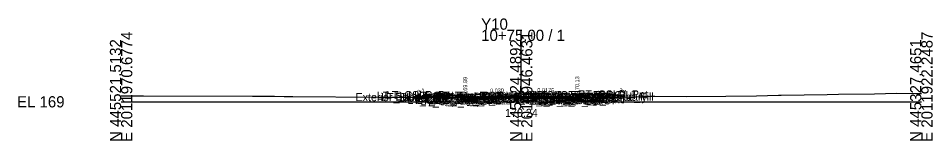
# Model space of a CAD drawing. Extents: x -26 to 203, y -10 to 3517.
# Drawn here: x -25.7 to 202.8, y 1490.3 to 1520.8 of the extents above; entities that cross this region are included whole.
import ezdxf

# ---------------------------------------------------------------- set-up
doc = ezdxf.new("R2010")
doc.units = 0
for name, color, linetype in [('Default', 7, 'Continuous'), ('Exist CMT Pavement', 7, 'Continuous'), ('Exist Cross Section Cell', 7, 'Continuous'), ('Exist XS Center Line Elevation Label', 7, 'Continuous'), ('Exist XS Ground Line', 7, 'Continuous'), ('Prop CMT Conc Surface', 7, 'Continuous'), ('Prop CMT Concrete Structures', 7, 'Continuous'), ('Prop CMT Pvmt Course 1', 7, 'Continuous'), ('Prop CMT Pvmt Course 1 CG', 7, 'Continuous'), ('Prop CMT Pvmt Course 1 Wedge', 7, 'Continuous'), ('Prop CMT Pvmt Course 2', 7, 'Continuous'), ('Prop CMT Pvmt Course 2 Wedge', 7, 'Continuous'), ('Prop CMT Pvmt Course 3', 7, 'Continuous'), ('Prop CMT Pvmt Surface', 7, 'Continuous'), ('Prop CMT Pvmt Wedge Surface 1', 7, 'Continuous'), ('Prop CMT Pvmt Wedge Surface 2', 7, 'Continuous'), ('Prop CMT Pvmt Wedge Surface 3', 7, 'Continuous'), ('Prop CMT Slope Grass', 7, 'Continuous'), ('Prop CMT Subgrade Earthwork', 7, 'Continuous'), ('Prop XS Earthwork Shape', 7, 'Continuous'), ('Prop XS Hydro Elevations', 7, 'Continuous'), ('Prop XS SE Text', 7, 'Continuous'), ('Prop XS Side Slope Text', 7, 'Continuous'), ('Prop XS Wedging', 7, 'Continuous'), ('Scratch_Level_0', 7, 'Continuous')]:
    doc.layers.add(name, color=color, linetype=linetype)

msp = doc.modelspace()

# ---------------------------------------------------------------- linework, layer by layer
at = {"layer": 'Exist CMT Pavement'}
for points in [[(100, 1501.24), (99.36, 1501.27), (98.78, 1501.28), (98.19, 1501.26), (89, 1500.95)], [(100, 1501.24), (110.86, 1500.87), (111, 1500.89)]]:
    msp.add_lwpolyline(points, dxfattribs=at)
at = {"layer": 'Exist Cross Section Cell'}
for p, q in [((100, 1500), (100, 1517.97)), ((0, 1500), (100, 1500)), ((100, 1500), (200, 1500))]:
    msp.add_line(p, q, dxfattribs=at)
at = {"layer": 'Exist XS Ground Line'}
msp.add_lwpolyline([(0, 1501.48), (5.57, 1501.49), (32.82, 1501.4), (35.89, 1501.4), (38.37, 1501.41), (40.72, 1501.35), (41.07, 1501.35), (42.89, 1501.29), (64.32, 1501.19), (70.55, 1501.16), (75.55, 1501.16), (82.83, 1501.17), (86.42, 1501.06), (87.64, 1500.91), (98.19, 1501.26), (98.78, 1501.28), (99.36, 1501.27), (100, 1501.24), (110.86, 1500.87), (111.9, 1501.01), (112.69, 1501.06), (114.28, 1501.06), (119.35, 1501.18), (121.12, 1501.18), (128.49, 1501.27), (132.3, 1501.37), (133.37, 1501.38), (141.42, 1501.32), (151.11, 1501.43), (158.83, 1501.46), (164.26, 1501.67), (164.97, 1501.66), (176.46, 1501.82), (179.29, 1501.88), (188.33, 1502.02), (193.75, 1502.15), (198.63, 1502.04), (200, 1502.05)], dxfattribs=at)
at = {"layer": 'Prop CMT Conc Surface'}
for points in [[(86, 1500.99), (86, 1501.49), (85.5, 1501.49)], [(114, 1501.16), (114, 1501.66), (114.5, 1501.66)], [(88, 1501.13), (86, 1500.99)], [(112, 1501.28), (114, 1501.16)]]:
    msp.add_lwpolyline(points, dxfattribs=at)
at = {"layer": 'Prop CMT Concrete Structures'}
for points in [[(88, 1501.13), (86, 1500.99), (86, 1501.49), (85.5, 1501.49)], [(85.5, 1501.49), (85.5, 1500.47), (88, 1500.55)], [(112, 1501.28), (114, 1501.16), (114, 1501.66), (114.5, 1501.66)], [(114.5, 1501.66), (114.5, 1500.65), (112, 1500.7)], [(88, 1500.55), (88, 1501.13)], [(112, 1500.7), (112, 1501.28)]]:
    msp.add_lwpolyline(points, dxfattribs=at)
at = {"layer": 'Prop CMT Pvmt Course 1'}
for points in [[(100, 1501.49), (88, 1501.13)], [(100, 1501.24), (100, 1501.49)], [(100, 1501.49), (112, 1501.28)], [(100, 1501.24), (100, 1501.49)], [(88, 1501.13), (88, 1500.88)], [(88, 1500.88), (89, 1500.91)], [(89, 1501.03), (100, 1501.36)], [(89, 1500.91), (89, 1501.03)], [(100, 1501.36), (100, 1501.24), (100, 1501.24)], [(111, 1501.17), (100, 1501.36)], [(100, 1501.36), (100, 1501.24), (100, 1501.24)], [(111, 1501.05), (111, 1501.17)], [(112, 1501.03), (111, 1501.05)], [(112, 1501.28), (112, 1501.03)]]:
    msp.add_lwpolyline(points, dxfattribs=at)
at = {"layer": 'Prop CMT Pvmt Course 1 CG'}
for points in [[(88, 1500.55), (85, 1500.46), (84.7, 1500.15)], [(84.7, 1500.15), (88, 1500.25)], [(88, 1500.25), (88, 1500.55)], [(112, 1500.7), (115, 1500.64), (115.3, 1500.35)], [(112, 1500.4), (112, 1500.7)], [(115.3, 1500.35), (112, 1500.4)]]:
    msp.add_lwpolyline(points, dxfattribs=at)
at = {"layer": 'Prop CMT Pvmt Course 1 Wedge'}
for points in [[(89, 1501.03), (98.19, 1501.31), (98.78, 1501.33), (99.36, 1501.34), (100, 1501.36)], [(100, 1501.24), (99.36, 1501.27), (98.78, 1501.28), (98.19, 1501.26), (89, 1500.95)], [(89, 1500.95), (89, 1501.03)], [(100, 1501.36), (100, 1501.24)], [(100, 1501.36), (110.86, 1501.17), (111, 1501.17)], [(100, 1501.24), (100, 1501.36)], [(111, 1501.05), (110.86, 1501.05), (100.28, 1501.23), (100, 1501.24)], [(111, 1501.17), (111, 1501.05)]]:
    msp.add_lwpolyline(points, dxfattribs=at)
at = {"layer": 'Prop CMT Pvmt Course 2'}
for points in [[(89, 1500.91), (88, 1500.88)], [(88, 1500.88), (88, 1500.63)], [(88, 1500.63), (89, 1500.66)], [(89, 1500.66), (89, 1500.91)], [(111, 1500.8), (111, 1501.05)], [(111, 1501.05), (112, 1501.03)], [(112, 1500.78), (111, 1500.8)], [(112, 1501.03), (112, 1500.78)]]:
    msp.add_lwpolyline(points, dxfattribs=at)
at = {"layer": 'Prop CMT Pvmt Course 2 Wedge'}
for points in [[(111, 1500.89), (110.86, 1500.87), (100.28, 1501.23)], [(100.28, 1501.23), (110.86, 1501.05)], [(110.86, 1501.05), (111, 1501.05)], [(111, 1501.05), (111, 1500.89)]]:
    msp.add_lwpolyline(points, dxfattribs=at)
at = {"layer": 'Prop CMT Pvmt Course 3'}
for points in [[(89, 1500.66), (88, 1500.63)], [(88, 1500.63), (88, 1500.25)], [(88, 1500.25), (89, 1500.28)], [(89, 1500.28), (89, 1500.66)], [(111, 1500.8), (112, 1500.78)], [(111, 1500.42), (111, 1500.8)], [(112, 1500.4), (111, 1500.42)], [(112, 1500.78), (112, 1500.4)]]:
    msp.add_lwpolyline(points, dxfattribs=at)
at = {"layer": 'Prop CMT Pvmt Surface'}
for points in [[(100, 1501.49), (88, 1501.13)], [(100, 1501.49), (112, 1501.28)]]:
    msp.add_lwpolyline(points, dxfattribs=at)
at = {"layer": 'Prop CMT Pvmt Wedge Surface 1'}
for points in [[(88, 1500.88), (88, 1501.13)], [(89, 1500.91), (88, 1500.88)], [(100, 1501.36), (89, 1501.03)], [(89, 1501.03), (89, 1500.91)], [(100, 1501.36), (111, 1501.17)], [(111, 1501.17), (111, 1501.05)], [(111, 1501.05), (112, 1501.03)], [(112, 1501.03), (112, 1501.28)]]:
    msp.add_lwpolyline(points, dxfattribs=at)
at = {"layer": 'Prop CMT Pvmt Wedge Surface 2'}
for points in [[(100, 1501.24), (88, 1500.88)], [(88, 1500.88), (88, 1501.13)], [(100, 1501.24), (112, 1501.03)], [(112, 1501.03), (112, 1501.28)]]:
    msp.add_lwpolyline(points, dxfattribs=at)
at = {"layer": 'Prop CMT Pvmt Wedge Surface 3'}
for points in [[(88, 1500.63), (88, 1501.13)], [(100, 1500.99), (88, 1500.63)], [(100, 1500.99), (112, 1500.78)], [(112, 1500.78), (112, 1501.28)]]:
    msp.add_lwpolyline(points, dxfattribs=at)
at = {"layer": 'Prop CMT Slope Grass'}
for points in [[(85.5, 1501.49), (76, 1501.68), (74.45, 1501.16)], [(114.5, 1501.66), (124, 1501.85), (125.84, 1501.24)]]:
    msp.add_lwpolyline(points, dxfattribs=at)
at = {"layer": 'Prop CMT Subgrade Earthwork'}
for points in [[(88, 1500.25), (84.7, 1500.15), (83.32, 1501.53)], [(112, 1500.4), (115.3, 1500.35), (116.66, 1501.71)], [(89, 1500.28), (88, 1500.25)], [(89, 1500.28), (89.01, 1500.96)], [(111, 1500.42), (111, 1500.89)], [(111, 1500.42), (112, 1500.4)]]:
    msp.add_lwpolyline(points, dxfattribs=at)
at = {"layer": 'Prop XS Earthwork Shape'}
for points in [[(83.32, 1501.53), (76, 1501.68), (74.45, 1501.16), (75.55, 1501.16), (82.83, 1501.17), (83.71, 1501.14)], [(116.05, 1501.1), (116.66, 1501.71), (124, 1501.85), (125.84, 1501.24), (121.12, 1501.18), (119.35, 1501.18)], [(85.5, 1500.47), (88, 1500.55), (88, 1500.92), (89, 1500.95), (89.01, 1500.96), (89, 1500.28), (88, 1500.25), (84.7, 1500.15), (83.71, 1501.14), (85.5, 1501.09)], [(86, 1500.99), (86, 1501.07), (85.5, 1501.09), (85.5, 1500.47), (88, 1500.55), (88, 1500.92), (87.64, 1500.91), (86.63, 1501.03)], [(86, 1500.99), (86, 1501.07), (86.42, 1501.06), (86.63, 1501.03)], [(114.5, 1500.65), (112, 1500.7), (112, 1501.02), (111.9, 1501.01), (111, 1500.89), (111, 1500.42), (112, 1500.4), (115.3, 1500.35), (116.05, 1501.1), (114.5, 1501.06)], [(112, 1501.02), (112.69, 1501.06), (114.28, 1501.06), (114.5, 1501.06), (114.5, 1500.65), (112, 1500.7)]]:
    msp.add_lwpolyline(points, close=True, dxfattribs=at)
at = {"layer": 'Prop XS Wedging'}
for p, q in [((98.19, 1501.31), (89, 1501.03)), ((89, 1501.03), (89, 1500.95)), ((98.78, 1501.33), (98.19, 1501.31)), ((99.36, 1501.34), (98.78, 1501.33)), ((100, 1501.36), (99.36, 1501.34)), ((110.86, 1501.17), (100, 1501.36)), ((100, 1501.36), (100, 1501.24)), ((100, 1501.24), (100, 1501.36)), ((100, 1501.24), (100.28, 1501.23)), ((110.86, 1501.05), (100.28, 1501.23)), ((100.28, 1501.23), (110.86, 1501.05)), ((111, 1501.17), (110.86, 1501.17)), ((110.86, 1501.05), (110.87, 1501.05)), ((110.87, 1501.05), (111, 1501.05)), ((111, 1501.05), (111, 1501.17)), ((111, 1500.89), (111, 1501.05))]:
    msp.add_line(p, q, dxfattribs=at)
for points in [[(89, 1500.95), (89.01, 1500.96), (98.19, 1501.26), (98.78, 1501.28)], [(98.78, 1501.28), (99.36, 1501.27), (100, 1501.24)], [(100.28, 1501.23), (110.86, 1500.87), (111, 1500.89)], [(111, 1501.05), (110.87, 1501.05), (110.86, 1501.05)]]:
    msp.add_lwpolyline(points, dxfattribs=at)

# ---------------------------------------------------------------- texts
at = {"layer": 'Default'}
msp.add_text('-', height=0.0001, dxfattribs=at).set_placement((0, 1500))
at = {"layer": 'Exist Cross Section Cell'}
for s, p in [('Y10', (90, 1517.97)), ('10+75.00 / 1', (90, 1515.17)), ('EL 169', (-26, 1498.6))]:
    msp.add_text(s, height=2.8, dxfattribs=at).set_placement(p)
for s, p in [('N 445521.5132', (0, 1490)), ('E 2011970.6774', (2.8, 1490)), ('N 445424.4892', (100, 1490)), ('E 2011946.4631', (102.8, 1490)), ('N 445327.4651', (200, 1490)), ('E 2011922.2487', (202.8, 1490))]:
    msp.add_text(s, height=2.8, rotation=90, dxfattribs=at).set_placement(p)
at = {"layer": 'Exist XS Center Line Elevation Label'}
msp.add_text('170.24', height=2, dxfattribs=at).set_placement((95.96, 1496.24))
at = {"layer": 'Prop XS Hydro Elevations'}
for s, p in [('170.13', (114.5, 1502.13)), ('169.99', (86.5, 1501.99))]:
    msp.add_text(s, height=1, rotation=90, dxfattribs=at).set_placement(p)
at = {"layer": 'Prop XS SE Text'}
for s, rotation, p in [('0.030', 1.7184, (92.22, 1502.26)), ('0.0175', 358.8542, (104.01, 1502.41))]:
    msp.add_text(s, height=1, rotation=rotation, dxfattribs=at).set_placement(p)
at = {"layer": 'Prop XS Side Slope Text'}
for rotation, p in [(18.4332, (74.24, 1501.88)), (341.5668, (124.36, 1502.49))]:
    msp.add_text('3:1', height=1, rotation=rotation, dxfattribs=at).set_placement(p)
at = {"layer": 'Scratch_Level_0'}
for s, p in [('Exterior Boundary', (58.59, 1500.16)), ('LT_Sub_Trench_Out_DLT', (63.89, 1500.53)), ('LT_Slope_Fill', (64.97, 1500.16)), ('LT_CSLP_Pnt', (66.17, 1500.68)), ('LT_CG1_Shelf_Out', (71.55, 1499.46)), ('LT_CG_Top_Face', (73.26, 1500.49)), ('LT_CG_Top_BOC', (73.78, 1500.49)), ('LT_CG_Bot_BOC', (73.81, 1499.47)), ('LT_PV_Sub_Tie_Out', (73.96, 1499.96)), ('LT_CG_Top_Gut', (74.24, 1499.99)), ('LT_PV_OEEOP_EG', (76.54, 1499.95)), ('LT_CG_Bot_IE', (77.91, 1499.55)), ('LT_PV2_OEOT', (78.17, 1499.88)), ('LT_PV3_OEOT', (78.17, 1499.63)), ('LT_PV2_OEEOP', (78.31, 1499.91)), ('LT_PV3_OEEOP', (78.31, 1499.66)), ('LT_PV1_OEOT', (78.74, 1500.13)), ('LT_PV1_OEEOP', (78.87, 1500.03)), ('RT_PV_IEEOP_EG', (88.14, 1500.24)), ('LT_PV_IEEOP_EG', (88.19, 1500.24)), ('RT_PV2_IEEOP', (89.91, 1500.24)), ('RT_PV3_IEEOP', (89.91, 1499.99)), ('LT_PV2_IEEOP', (89.95, 1500.24)), ('LT_PV3_IEEOP', (89.95, 1499.99)), ('RT_PV1_IEEOP', (90.47, 1500.36)), ('LT_PV1_IEEOP', (90.52, 1500.36)), ('PV2_PGL', (93.91, 1500.24)), ('PV1_PGL', (94.47, 1500.49)), ('RT_PV_Sub_Tie_Out', (95.88, 1499.89)), ('RT_Sub_Trench_Out_DLT', (97.18, 1500.71)), ('RT_PV_OEEOP_EG', (98.5, 1499.89)), ('RT_Sub_OEEOP', (100.17, 1499.42)), ('RT_PV2_OEEOP', (100.26, 1500.05)), ('RT_PV3_OEEOP', (100.26, 1499.8)), ('RT_PV1_OEEOP', (100.83, 1500.17)), ('RT_CG_Top_Face', (101.21, 1500.66)), ('RT_CG1_Shelf_Out', (101.5, 1499.64)), ('RT_CG_Bot_IE', (101.87, 1499.7)), ('RT_Sub_OEOT', (102.03, 1499.4)), ('RT_PV2_OEOT', (102.13, 1500.03)), ('RT_PV3_OEOT', (102.13, 1499.78)), ('RT_CG_Top_Gut', (102.19, 1500.16)), ('RT_PV1_OEOT', (102.69, 1500.28)), ('RT_CG_Top_BOC', (102.74, 1500.66)), ('RT_CG_Bot_BOC', (102.77, 1499.65)), ('Exterior Boundary', (109.99, 1500.24)), ('RT_CSLP_Pnt', (114.13, 1500.85)), ('RT_Slope_Fill', (116.32, 1500.24)), ('LT_Sub_OEOP', (74.81, 1499.15)), ('LT_Sub_OEOT', (78.08, 1499.25)), ('LT_Sub_OEEOP', (78.21, 1499.28)), ('RT_Sub_OEOP', (105.36, 1499.35))]:
    msp.add_text(s, height=2, dxfattribs=at).set_placement(p)

doc.saveas('drawing.dxf')
